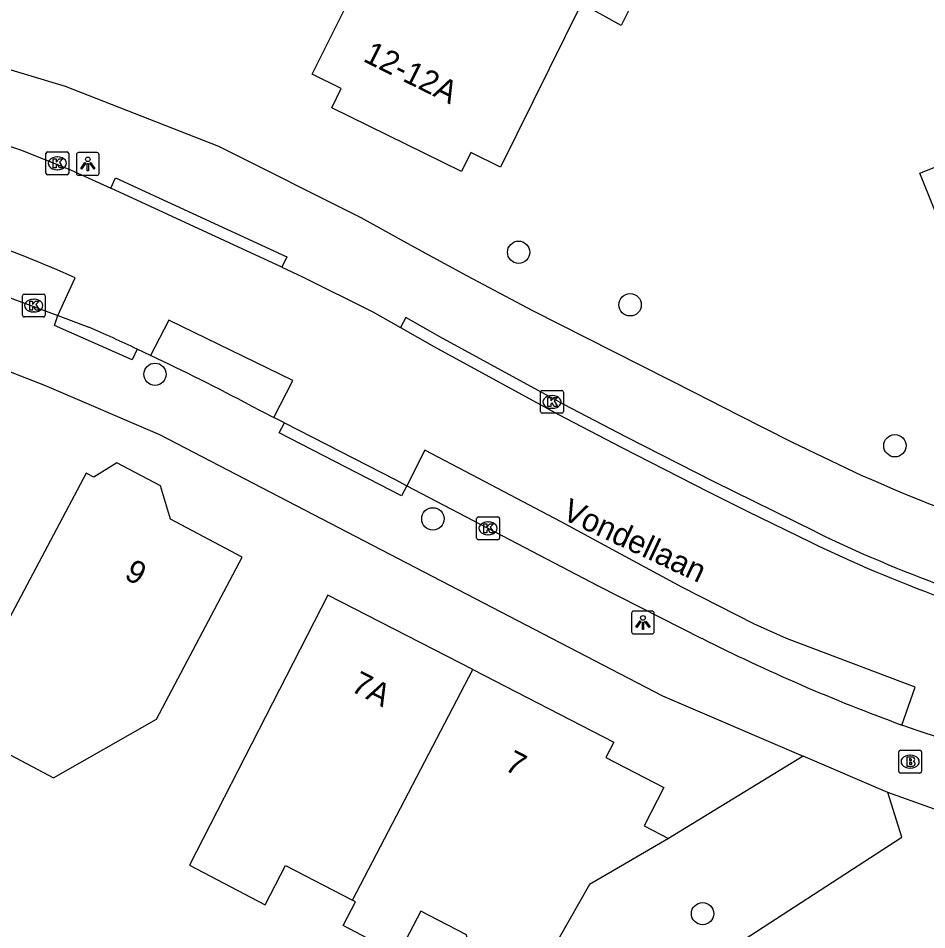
# Model space of a CAD drawing. Extents: x 161354 to 161876, y 382161 to 382804.
# Drawn here: x 161684.52 to 161724.32, y 382471.39 to 382511.32 of the extents above; entities that cross this region are included whole.
import ezdxf

# ---------------------------------------------------------------- set-up
doc = ezdxf.new("R2010")
doc.units = 0
for name, color, linetype in [('IMGEO_Boom', 7, 'Continuous'), ('IMGEO_Brandkraan', 7, 'Continuous'), ('IMGEO_Groenvoorziening', 7, 'Continuous'), ('IMGEO_Kolk', 7, 'Continuous'), ('IMGEO_Lichtpunt', 7, 'Continuous'), ('IMGEO_Openbare_ruimte_label', 7, 'Continuous'), ('IMGEO_Pand', 7, 'Continuous'), ('IMGEO_Pand_nummerreeks', 7, 'Continuous'), ('IMGEO_Rijbaan_lokaal_open', 7, 'Continuous'), ('IMGEO_Voetpad_open', 7, 'Continuous')]:
    doc.layers.add(name, color=color, linetype=linetype)

msp = doc.modelspace()

# ---------------------------------------------------------------- linework, layer by layer
at = {"layer": 'IMGEO_Boom'}
for centre in [(161706.441, 382501.07), (161711.325, 382498.768), (161690.51, 382495.726), (161722.927, 382492.596), (161702.684, 382489.393), (161714.501, 382472.1)]:
    msp.add_circle(centre, 0.489, dxfattribs=at)
at = {"layer": 'IMGEO_Brandkraan'}
for p, q in [((161723.169, 382479.259), (161724.021, 382479.259)), ((161723.094, 382478.333), (161723.094, 382479.185)), ((161723.582, 382479.039), (161723.607, 382479.039)), ((161724.095, 382479.185), (161724.095, 382478.333)), ((161723.605, 382478.479), (161723.58, 382478.479)), ((161724.021, 382478.259), (161723.169, 382478.259))]:
    msp.add_line(p, q, dxfattribs=at)
for points in [[(161723.169, 382479.259), (161724.021, 382479.259)], [(161723.094, 382478.333), (161723.094, 382479.185)], [(161723.442, 382478.959), (161723.442, 382478.559), (161723.655, 382478.559)], [(161723.673, 382478.959), (161723.442, 382478.959)], [(161723.621, 382478.878), (161723.567, 382478.878), (161723.567, 382478.802)], [(161724.095, 382479.185), (161724.095, 382478.333)], [(161723.567, 382478.802), (161723.62, 382478.802)], [(161723.629, 382478.726), (161723.567, 382478.726), (161723.567, 382478.645)], [(161723.567, 382478.645), (161723.629, 382478.645)], [(161724.021, 382478.259), (161723.169, 382478.259)]]:
    msp.add_lwpolyline(points, dxfattribs=at)
for centre, radius, start, end in [((161723.171, 382479.183), 0.0765, 91.552, 178.448), ((161723.171, 382479.183), 0.0765, 91.552, 178.448), ((161724.019, 382479.183), 0.0765, 1.552, 88.448), ((161724.019, 382479.183), 0.0765, 1.552, 88.448), ((161723.622, 382478.84), 0.0379, 267.8285, 90.9355), ((161723.677, 382478.814), 0.145, 59.4692, 91.5367), ((161723.702, 382478.861), 0.0922, 285.5137, 58.1501), ((161723.63, 382478.685), 0.0404, 269.8759, 90.5077), ((161723.661, 382478.81), 0.251, 268.6676, 293.5347), ((161723.707, 382478.669), 0.105, 301.3115, 78.989), ((161723.171, 382478.335), 0.0765, 181.552, 268.448), ((161723.171, 382478.335), 0.0765, 181.552, 268.448), ((161724.019, 382478.335), 0.0765, 271.552, 358.448), ((161724.019, 382478.335), 0.0765, 271.552, 358.448)]:
    msp.add_arc(centre, radius, start, end, dxfattribs=at)
for centre, major_axis, ratio, start_param, end_param in [((161723.581, 382478.759), (-0.387, 0.002), 0.722429, 4.712389, 7.853982), ((161723.606, 382478.759), (-0.39, 0.002), 0.717154, 1.570796, 4.712389)]:
    msp.add_ellipse(centre, major_axis=major_axis, ratio=ratio, start_param=start_param, end_param=end_param, dxfattribs=at)
at = {"layer": 'IMGEO_Groenvoorziening'}
msp.add_lwpolyline([(161718.908, 382479.002), (161713.011, 382475.39)], dxfattribs=at)
at = {"layer": 'IMGEO_Kolk'}
for p, q in [((161685.733, 382504.541), (161685.733, 382505.393)), ((161685.808, 382505.467), (161686.66, 382505.467)), ((161686.221, 382505.247), (161686.246, 382505.247)), ((161686.734, 382505.393), (161686.734, 382504.541)), ((161686.66, 382504.467), (161685.808, 382504.467)), ((161686.244, 382504.687), (161686.219, 382504.687)), ((161684.774, 382499.235), (161685.626, 382499.235)), ((161684.699, 382498.309), (161684.699, 382499.161)), ((161685.187, 382499.015), (161685.212, 382499.015)), ((161685.7, 382499.161), (161685.7, 382498.309)), ((161685.21, 382498.455), (161685.185, 382498.455)), ((161685.626, 382498.235), (161684.774, 382498.235)), ((161707.403, 382494.09), (161707.403, 382494.942)), ((161707.478, 382495.016), (161708.33, 382495.016)), ((161707.891, 382494.796), (161707.916, 382494.796)), ((161708.404, 382494.942), (161708.404, 382494.09)), ((161708.33, 382494.016), (161707.478, 382494.016)), ((161707.914, 382494.236), (161707.889, 382494.236)), ((161704.603, 382488.554), (161704.603, 382489.406)), ((161704.678, 382489.48), (161705.53, 382489.48)), ((161705.091, 382489.26), (161705.116, 382489.26)), ((161705.604, 382489.406), (161705.604, 382488.554)), ((161705.53, 382488.48), (161704.678, 382488.48)), ((161705.114, 382488.7), (161705.089, 382488.7))]:
    msp.add_line(p, q, dxfattribs=at)
for points in [[(161685.733, 382504.541), (161685.733, 382505.393)], [(161685.808, 382505.467), (161686.66, 382505.467)], [(161686.054, 382505.167), (161686.177, 382505.167), (161686.177, 382505.016), (161686.307, 382505.167), (161686.471, 382505.167), (161686.325, 382505.016), (161686.478, 382504.767), (161686.326, 382504.767), (161686.241, 382504.931), (161686.177, 382504.864), (161686.177, 382504.767), (161686.054, 382504.767), (161686.054, 382505.167)], [(161686.734, 382505.393), (161686.734, 382504.541)], [(161686.66, 382504.467), (161685.808, 382504.467)], [(161684.774, 382499.235), (161685.626, 382499.235)], [(161684.699, 382498.309), (161684.699, 382499.161)], [(161685.02, 382498.935), (161685.143, 382498.935), (161685.143, 382498.784), (161685.273, 382498.935), (161685.437, 382498.935), (161685.291, 382498.784), (161685.444, 382498.535), (161685.292, 382498.535), (161685.207, 382498.699), (161685.143, 382498.632), (161685.143, 382498.535), (161685.02, 382498.535), (161685.02, 382498.935)], [(161685.7, 382499.161), (161685.7, 382498.309)], [(161685.626, 382498.235), (161684.774, 382498.235)], [(161707.403, 382494.09), (161707.403, 382494.942)], [(161707.478, 382495.016), (161708.33, 382495.016)], [(161708.404, 382494.942), (161708.404, 382494.09)], [(161707.724, 382494.716), (161707.847, 382494.716), (161707.847, 382494.565), (161707.977, 382494.716), (161708.141, 382494.716), (161707.995, 382494.565), (161708.148, 382494.316), (161707.996, 382494.316), (161707.911, 382494.48), (161707.847, 382494.413), (161707.847, 382494.316), (161707.724, 382494.316), (161707.724, 382494.716)], [(161708.33, 382494.016), (161707.478, 382494.016)], [(161704.603, 382488.554), (161704.603, 382489.406)], [(161704.678, 382489.48), (161705.53, 382489.48)], [(161705.604, 382489.406), (161705.604, 382488.554)], [(161704.924, 382489.18), (161705.047, 382489.18), (161705.047, 382489.029), (161705.177, 382489.18), (161705.341, 382489.18), (161705.195, 382489.029), (161705.348, 382488.78), (161705.196, 382488.78), (161705.111, 382488.944), (161705.047, 382488.877), (161705.047, 382488.78), (161704.924, 382488.78), (161704.924, 382489.18)], [(161705.53, 382488.48), (161704.678, 382488.48)]]:
    msp.add_lwpolyline(points, dxfattribs=at)
for centre, start, end in [((161685.81, 382505.391), 91.552, 178.448), ((161685.81, 382505.391), 91.552, 178.448), ((161686.658, 382505.391), 1.552, 88.448), ((161686.658, 382505.391), 1.552, 88.448), ((161685.81, 382504.543), 181.552, 268.448), ((161685.81, 382504.543), 181.552, 268.448), ((161686.658, 382504.543), 271.552, 358.448), ((161686.658, 382504.543), 271.552, 358.448), ((161684.776, 382499.159), 91.552, 178.448), ((161684.776, 382499.159), 91.552, 178.448), ((161685.624, 382499.159), 1.552, 88.448), ((161685.624, 382499.159), 1.552, 88.448), ((161684.776, 382498.311), 181.552, 268.448), ((161684.776, 382498.311), 181.552, 268.448), ((161685.624, 382498.311), 271.552, 358.448), ((161685.624, 382498.311), 271.552, 358.448), ((161707.48, 382494.94), 91.552, 178.448), ((161707.48, 382494.94), 91.552, 178.448), ((161708.328, 382494.94), 1.552, 88.448), ((161708.328, 382494.94), 1.552, 88.448), ((161707.48, 382494.092), 181.552, 268.448), ((161707.48, 382494.092), 181.552, 268.448), ((161708.328, 382494.092), 271.552, 358.448), ((161708.328, 382494.092), 271.552, 358.448), ((161704.68, 382489.404), 91.552, 178.448), ((161704.68, 382489.404), 91.552, 178.448), ((161705.528, 382489.404), 1.552, 88.448), ((161705.528, 382489.404), 1.552, 88.448), ((161704.68, 382488.556), 181.552, 268.448), ((161704.68, 382488.556), 181.552, 268.448), ((161705.528, 382488.556), 271.552, 358.448), ((161705.528, 382488.556), 271.552, 358.448)]:
    msp.add_arc(centre, 0.0765, start, end, dxfattribs=at)
for centre, major_axis, ratio, start_param, end_param in [((161686.22, 382504.967), (-0.387, 0.002), 0.722429, 4.712389, 7.853982), ((161686.245, 382504.967), (-0.39, 0.002), 0.717154, 1.570796, 4.712389), ((161685.186, 382498.735), (-0.387, 0.002), 0.722429, 4.712389, 7.853982), ((161685.211, 382498.735), (-0.39, 0.002), 0.717154, 1.570796, 4.712389), ((161707.89, 382494.516), (-0.387, 0.002), 0.722429, 4.712389, 7.853982), ((161707.915, 382494.516), (-0.39, 0.002), 0.717154, 1.570796, 4.712389), ((161705.09, 382488.98), (-0.387, 0.002), 0.722429, 4.712389, 7.853982), ((161705.115, 382488.98), (-0.39, 0.002), 0.717154, 1.570796, 4.712389)]:
    msp.add_ellipse(centre, major_axis=major_axis, ratio=ratio, start_param=start_param, end_param=end_param, dxfattribs=at)
at = {"layer": 'IMGEO_Lichtpunt'}
for p, q in [((161687.067, 382505.341), (161687.067, 382504.534)), ((161687.067, 382505.341), (161687.067, 382504.534)), ((161687.969, 382505.436), (161687.161, 382505.436)), ((161687.969, 382505.436), (161687.161, 382505.436)), ((161688.063, 382504.534), (161688.063, 382505.341)), ((161688.063, 382504.534), (161688.063, 382505.341)), ((161687.161, 382504.44), (161687.969, 382504.44)), ((161687.161, 382504.44), (161687.969, 382504.44)), ((161711.388, 382485.256), (161711.388, 382484.449)), ((161711.388, 382485.256), (161711.388, 382484.449)), ((161712.29, 382485.351), (161711.482, 382485.351)), ((161712.29, 382485.351), (161711.482, 382485.351)), ((161712.384, 382484.449), (161712.384, 382485.256)), ((161712.384, 382484.449), (161712.384, 382485.256)), ((161711.482, 382484.355), (161712.29, 382484.355)), ((161711.482, 382484.355), (161712.29, 382484.355))]:
    msp.add_line(p, q, dxfattribs=at)
for points in [[(161687.441, 382505.005), (161687.48, 382504.977), (161687.292, 382504.715), (161687.254, 382504.742), (161687.441, 382505.005)], [(161687.543, 382504.957), (161687.59, 382504.957), (161687.59, 382504.635), (161687.543, 382504.635), (161687.543, 382504.957)], [(161687.653, 382504.977), (161687.691, 382505.004), (161687.878, 382504.742), (161687.839, 382504.714), (161687.653, 382504.977)], [(161711.762, 382484.92), (161711.801, 382484.892), (161711.613, 382484.63), (161711.575, 382484.657), (161711.762, 382484.92)], [(161711.864, 382484.872), (161711.911, 382484.872), (161711.911, 382484.55), (161711.864, 382484.55), (161711.864, 382484.872)], [(161711.974, 382484.892), (161712.012, 382484.919), (161712.199, 382484.657), (161712.16, 382484.629), (161711.974, 382484.892)]]:
    msp.add_lwpolyline(points, dxfattribs=at)
for centre in [(161687.566, 382505.139), (161711.887, 382485.054)]:
    msp.add_circle(centre, 0.0994, dxfattribs=at)
for centre, start, end in [((161687.161, 382505.341), 90, 180), ((161687.161, 382505.341), 90, 180), ((161687.969, 382505.341), 0, 90), ((161687.969, 382505.341), 0, 90), ((161687.161, 382504.534), 180, 270), ((161687.161, 382504.534), 180, 270), ((161687.969, 382504.534), 270, 0), ((161687.969, 382504.534), 270, 360), ((161711.482, 382485.256), 90, 180), ((161711.482, 382485.256), 90, 180), ((161712.29, 382485.256), 0, 90), ((161712.29, 382485.256), 0, 90), ((161711.482, 382484.449), 180, 270), ((161711.482, 382484.449), 180, 270), ((161712.29, 382484.449), 270, 0), ((161712.29, 382484.449), 270, 360)]:
    msp.add_arc(centre, 0.0946, start, end, dxfattribs=at)
at = {"layer": 'IMGEO_Pand'}
for points in [[(161701.108, 382527.333), (161701.274, 382527.709), (161701.407, 382528.011), (161702.78, 382531.122), (161702.913, 382531.424), (161704.863, 382535.846), (161705.209, 382536.63), (161718.281, 382530.16), (161711.723, 382517.008), (161713.495, 382516.124), (161710.939, 382510.999), (161709.201, 382511.967), (161705.646, 382504.803), (161704.346, 382505.443), (161703.935, 382504.612), (161698.261, 382507.398), (161698.673, 382508.24), (161697.4, 382508.875), (161699.331, 382512.737), (161701.067, 382516.209)], [(161740.655, 382530.595), (161750.132, 382506.951), (161752.001, 382502.287), (161747.608, 382500), (161741.809, 382496.981), (161740.585, 382500), (161740.517, 382500.167), (161740.099, 382500), (161729.849, 382495.902), (161730.293, 382494.79), (161727.018, 382493.481), (161724.95, 382498.651), (161726.18, 382499.143), (161725.837, 382500), (161724.022, 382504.528), (161728.664, 382506.388), (161735.151, 382508.988), (161728.418, 382525.789), (161735.075, 382528.457)], [(161690.573, 382480.619), (161694.333, 382487.718), (161691.193, 382489.381), (161690.745, 382490.839), (161688.84, 382491.848), (161687.832, 382491.216), (161687.493, 382491.396), (161683.726, 382484.284), (161683.885, 382484.2), (161681.819, 382480.303), (161686.068, 382478.054), (161690.573, 382480.619)], [(161704.428, 382482.795), (161698.082, 382486.058), (161692.025, 382474.218), (161695.33, 382472.493), (161696.228, 382474.214), (161699.158, 382472.686)], [(161699.158, 382472.686), (161704.428, 382482.795)], [(161704.428, 382482.795), (161710.614, 382479.614), (161710.267, 382478.938), (161712.804, 382477.633), (161711.935, 382475.943), (161713.011, 382475.39)], [(161713.011, 382475.39), (161710.549, 382473.96), (161709.541, 382473.374), (161708.224, 382471.041)], [(161704.376, 382469.995), (161704.159, 382471.171), (161702.916, 382471.819), (161702.158, 382472.215), (161701.167, 382470.315), (161698.747, 382471.577), (161699.289, 382472.618), (161699.158, 382472.686)]]:
    msp.add_lwpolyline(points, dxfattribs=at)
at = {"layer": 'IMGEO_Rijbaan_lokaal_open'}
for points in [[(161674.333, 382508.996), (161677.108, 382508.026), (161679.107, 382507.366), (161681.884, 382506.459), (161683.272, 382506.002), (161684.661, 382505.544), (161686.809, 382504.682), (161688.569, 382503.883)], [(161696.072, 382500.419), (161688.569, 382503.883)], [(161696.072, 382500.419), (161696.974, 382500), (161700.052, 382498.454), (161701.262, 382497.773)], [(161686.249, 382498.297), (161687.01, 382499.945)], [(161686.249, 382498.297), (161687.609, 382497.792)], [(161695.713, 382493.839), (161696.542, 382495.455), (161691.119, 382498.101), (161690.311, 382496.555)], [(161701.262, 382497.773), (161702.751, 382496.934), (161708.189, 382493.967), (161710.935, 382492.532), (161714.753, 382490.583), (161716.458, 382489.726), (161719.242, 382488.369)], [(161690.311, 382496.555), (161689.729, 382496.829)], [(161696.181, 382493.599), (161695.713, 382493.839)], [(161696.181, 382493.599), (161701.035, 382491.11), (161701.544, 382490.843)], [(161723.236, 382480.362), (161723.813, 382482.015), (161718.183, 382484.152), (161716.769, 382484.785), (161713.618, 382486.383), (161710.568, 382488.031), (161708.308, 382489.257), (161704.396, 382491.323), (161702.326, 382492.399), (161701.544, 382490.843)], [(161726.799, 382479.176), (161723.942, 382480.108), (161723.236, 382480.362)]]:
    msp.add_lwpolyline(points, dxfattribs=at)
for centre, radius, start, end in [((161666.702, 382455.35), 49.001, 65.516, 76.3088), ((161643.812, 382398.56), 108.468, 64.95531, 66.18529), ((161746.351, 382544.343), 62.193, 244.15902, 249.87334)]:
    msp.add_arc(centre, radius, start, end, dxfattribs=at)
at = {"layer": 'IMGEO_Voetpad_open'}
for points in [[(161671.192, 382513.811), (161672.294, 382513.039), (161676.079, 382511.506), (161686.582, 382508.346), (161693.296, 382505.713), (161699.526, 382502.596), (161701.857, 382501.312), (161704.194, 382500.041), (161707.056, 382498.523), (161714.17, 382494.92), (161716.027, 382493.968), (161718.402, 382492.765), (161721.484, 382491.299)], [(161688.569, 382503.883), (161688.779, 382504.336), (161696.282, 382500.872), (161696.072, 382500.419)], [(161678.45, 382501.003), (161681.661, 382500), (161686.249, 382498.297)], [(161669.342, 382500.214), (161670.239, 382500), (161676.089, 382498.604), (161680.55, 382497.241), (161685.666, 382495.251), (161690.713, 382493.092), (161712.747, 382481.646), (161718.908, 382479.002)], [(161689.729, 382496.829), (161689.509, 382496.361), (161686.101, 382497.862), (161686.249, 382498.297)], [(161719.46, 382488.819), (161714.98, 382491.028), (161711.162, 382492.977), (161708.428, 382494.406), (161702.99, 382497.373), (161701.505, 382498.21), (161701.262, 382497.773)], [(161694.691, 382494.363), (161695.713, 382493.839)], [(161701.544, 382490.843), (161701.317, 382490.398), (161695.954, 382493.154), (161696.181, 382493.599)], [(161701.544, 382490.843), (161709.924, 382486.455), (161714.468, 382484.16)], [(161722.614, 382477.411), (161718.908, 382479.002)], [(161714.949, 382470.071), (161723.237, 382475.454), (161722.614, 382477.411)], [(161727.934, 382475.503), (161722.614, 382477.411)]]:
    msp.add_lwpolyline(points, dxfattribs=at)
for centre, radius, start, end in [((161641.429, 382393.408), 114.144, 62.18466, 64.64339), ((161753.222, 382562.309), 77.78, 245.91775, 251.24734), ((161746.285, 382544.176), 61.513, 244.14624, 249.87736), ((161750.885, 382556.211), 80.731, 243.18667, 249.97209)]:
    msp.add_arc(centre, radius, start, end, dxfattribs=at)

# ---------------------------------------------------------------- texts
at = {"layer": 'IMGEO_Openbare_ruimte_label'}
msp.add_text('Vondellaan', height=1, rotation=334.9208, dxfattribs=at).set_placement((161708.286, 382489.412))
at = {"layer": 'IMGEO_Pand_nummerreeks'}
for s, rotation, p in [('12-12A', 333.4892, (161699.583, 382509.462)), ('9', 331.7322, (161689.118, 382486.798)), ('7A', 332.7876, (161699.039, 382481.878)), ('7', 332.7902, (161705.776, 382478.415))]:
    msp.add_text(s, height=1, rotation=rotation, dxfattribs=at).set_placement(p)

doc.saveas('drawing.dxf')
